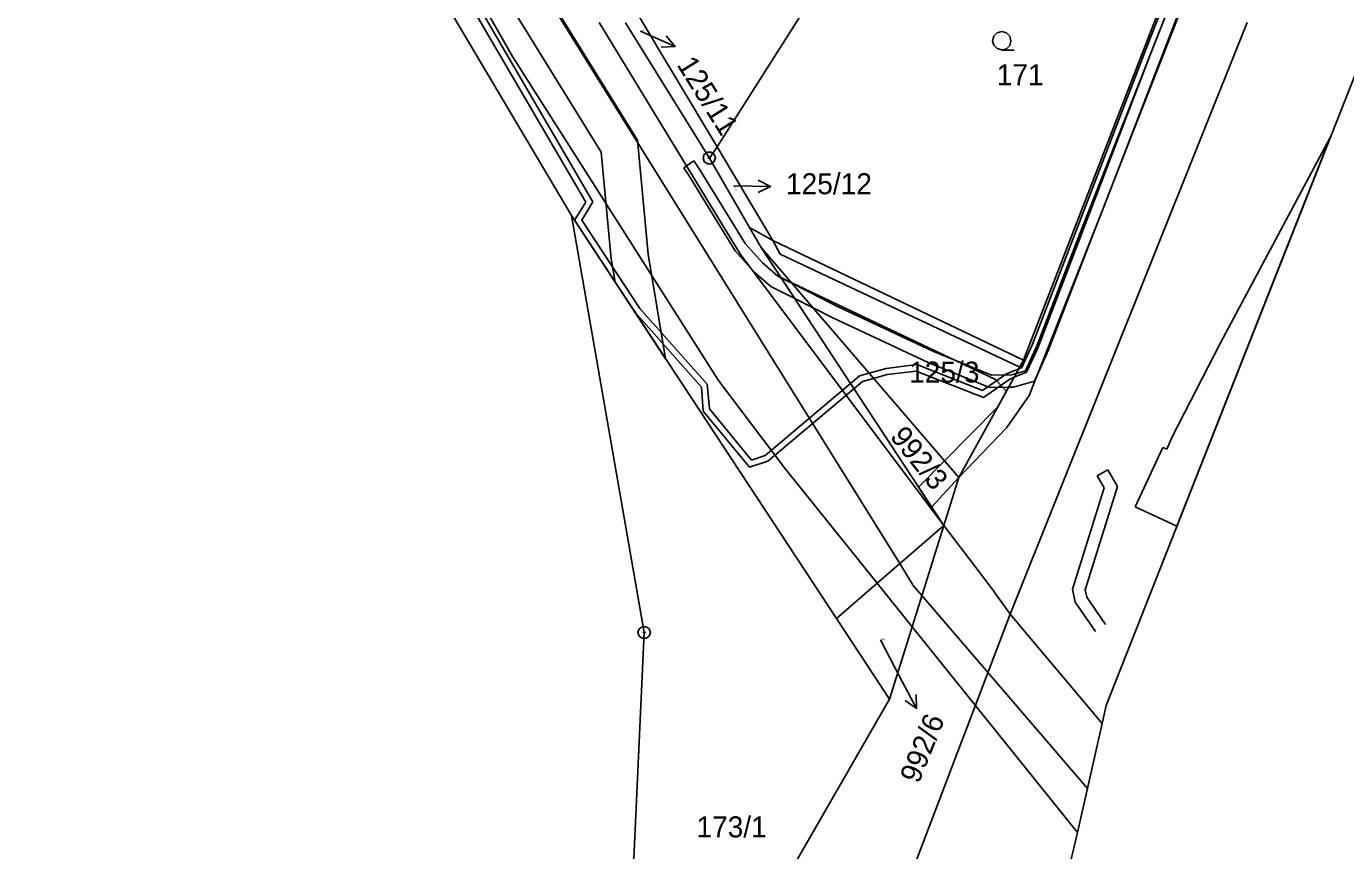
# Model space of a CAD drawing. Extents: x -755359 to -754474, y -1162585 to -1161655.
# Drawn here: x -754834.8 to -754728, y -1161971.6 to -1161904.8 of the extents above; entities that cross this region are included whole.
import ezdxf

# ---------------------------------------------------------------- set-up
doc = ezdxf.new("R2010")
doc.units = 0
for name, color, linetype in [('Vrstva 1', 7, 'Continuous'), ('Vrstva 11', 7, 'Continuous'), ('Vrstva 13', 7, 'Continuous'), ('Vrstva 2', 7, 'Continuous'), ('Vrstva 3', 7, 'Continuous'), ('Vrstva 4', 7, 'Continuous'), ('Vrstva 6', 7, 'Continuous'), ('Vrstva 7', 7, 'Continuous'), ('Vrstva 8', 7, 'Continuous')]:
    doc.layers.add(name, color=color, linetype=linetype)

msp = doc.modelspace()

# ---------------------------------------------------------------- linework, layer by layer
at = {"layer": 'Vrstva 1'}
for p, q in [((-754823.33, -1161865.1), (-754790.69, -1161920.17)), ((-754731.59, -1161873.64), (-754754.1, -1161931.89)), ((-754747.41, -1161959.83), (-754718.58, -1161886.73)), ((-754778.9, -1161914.6), (-754766.52, -1161895.09)), ((-754785.52, -1161903.56), (-754778.9, -1161914.6)), ((-754779.53, -1161915.51), (-754786.32, -1161904.57)), ((-754778.9, -1161914.6), (-754779.53, -1161915.51)), ((-754774.38, -1161922.19), (-754778.9, -1161914.6)), ((-754776.28, -1161921.13), (-754779.53, -1161915.51)), ((-754784.8, -1161953.94), (-754790.69, -1161920.17)), ((-754790.69, -1161920.17), (-754769.25, -1161952.8)), ((-754774.38, -1161922.19), (-754776.28, -1161921.13)), ((-754775.33, -1161922.76), (-754776.28, -1161921.13)), ((-754759.34, -1161941.39), (-754775.33, -1161922.76)), ((-754775.33, -1161922.76), (-754760.56, -1161945.27)), ((-754754.1, -1161931.89), (-754774.38, -1161922.19)), ((-754754.1, -1161931.89), (-754759.34, -1161941.39)), ((-754760.56, -1161945.27), (-754759.34, -1161941.39)), ((-754760.56, -1161945.27), (-754765.94, -1161949.93)), ((-754763.11, -1161953.46), (-754760.56, -1161945.27)), ((-754765.94, -1161949.93), (-754769.25, -1161952.8)), ((-754769.25, -1161952.8), (-754764.95, -1161959.34)), ((-754785.77, -1161974.89), (-754784.8, -1161953.94)), ((-754764.95, -1161959.34), (-754763.11, -1161953.46)), ((-754764.95, -1161959.34), (-754780.44, -1161986.21)), ((-754747.74, -1161961.29), (-754747.41, -1161959.83)), ((-754749.74, -1161970.12), (-754747.74, -1161961.29)), ((-754750.32, -1161972.64), (-754749.74, -1161970.12))]:
    msp.add_line(p, q, dxfattribs=at)
at = {"layer": 'Vrstva 11'}
for p, q in [((-754802.43, -1161886.78), (-754764.12, -1161948.35)), ((-754721.5, -1161894.13), (-754747.41, -1161959.83)), ((-754764.12, -1161948.35), (-754763.02, -1161950.13)), ((-754763.02, -1161950.13), (-754762.32, -1161950.94)), ((-754762.32, -1161950.94), (-754748.93, -1161966.56)), ((-754747.41, -1161959.83), (-754747.74, -1161961.29)), ((-754747.74, -1161961.29), (-754748.93, -1161966.56)), ((-754748.93, -1161966.56), (-754749.74, -1161970.12)), ((-754749.74, -1161970.12), (-754750.32, -1161972.64))]:
    msp.add_line(p, q, dxfattribs=at)
at = {"layer": 'Vrstva 13'}
for p, q in [((-754832.48, -1161837.94), (-754785.36, -1161914.05)), ((-754788.28, -1161915.03), (-754834.82, -1161839.85)), ((-754754.1, -1161931.89), (-754731.59, -1161873.64)), ((-754744.07, -1161906.36), (-754736.26, -1161886.5)), ((-754735.8, -1161886.68), (-754743.61, -1161906.54)), ((-754736.9, -1161891.63), (-754747.54, -1161919.33)), ((-754789.54, -1161919.07), (-754799.99, -1161901.15)), ((-754799.57, -1161900.89), (-754788.96, -1161919.06)), ((-754746.07, -1161912.78), (-754742.45, -1161903.59)), ((-754741.53, -1161903.95), (-754745.13, -1161913.14)), ((-754753.37, -1161930.59), (-754744.07, -1161906.36)), ((-754743.61, -1161906.54), (-754752.98, -1161930.96)), ((-754749.51, -1161921.57), (-754746.07, -1161912.78)), ((-754745.13, -1161913.14), (-754748.57, -1161921.93)), ((-754785.36, -1161914.05), (-754784.49, -1161923.29)), ((-754729.27, -1161913.84), (-754741.69, -1161945.32)), ((-754738.15, -1161930.48), (-754729.27, -1161913.84)), ((-754787.47, -1161923.67), (-754788.28, -1161915.03)), ((-754781.61, -1161916.31), (-754780.79, -1161915.73)), ((-754781.22, -1161916.86), (-754781.61, -1161916.31)), ((-754780.79, -1161915.73), (-754780.38, -1161916.32)), ((-754780.38, -1161916.32), (-754776.64, -1161922.43)), ((-754777.44, -1161923.03), (-754781.22, -1161916.86)), ((-754790.44, -1161920.55), (-754789.54, -1161919.07)), ((-754788.96, -1161919.06), (-754789.85, -1161920.53)), ((-754747.54, -1161919.33), (-754753.65, -1161934.74)), ((-754787.16, -1161925.55), (-754790.44, -1161920.55)), ((-754789.85, -1161920.53), (-754785.15, -1161927.69)), ((-754775.33, -1161922.76), (-754776.28, -1161921.13)), ((-754776.28, -1161921.13), (-754774.38, -1161922.19)), ((-754752.99, -1161930.67), (-754749.51, -1161921.57)), ((-754748.57, -1161921.93), (-754752.07, -1161931.05)), ((-754775.96, -1161924.7), (-754777.44, -1161923.03)), ((-754776.64, -1161922.43), (-754775.26, -1161923.98)), ((-754773.74, -1161925.19), (-754775.33, -1161922.76)), ((-754774.38, -1161922.19), (-754773.79, -1161923.28)), ((-754787.16, -1161925.55), (-754787.47, -1161923.67)), ((-754784.49, -1161923.29), (-754783.07, -1161931.76)), ((-754775.26, -1161923.98), (-754773.99, -1161925.07)), ((-754773.79, -1161923.28), (-754754.41, -1161932.45)), ((-754774.55, -1161925.91), (-754775.96, -1161924.7)), ((-754773.99, -1161925.07), (-754773.72, -1161925.21)), ((-754772.91, -1161925.58), (-754773.74, -1161925.19)), ((-754773.72, -1161925.21), (-754772.85, -1161925.65)), ((-754773.72, -1161925.21), (-754772.62, -1161926.89)), ((-754772.62, -1161926.89), (-754773.72, -1161925.21)), ((-754783.07, -1161931.76), (-754787.16, -1161925.55)), ((-754785.49, -1161928.08), (-754787.16, -1161925.55)), ((-754772.62, -1161926.89), (-754774.55, -1161925.91)), ((-754756.36, -1161933.45), (-754772.91, -1161925.58)), ((-754772.85, -1161925.65), (-754769.16, -1161927.53)), ((-754771.14, -1161927.65), (-754772.62, -1161926.89)), ((-754780.18, -1161934.05), (-754785.49, -1161928.08)), ((-754785.15, -1161927.69), (-754779.7, -1161933.83)), ((-754769.6, -1161928.43), (-754771.14, -1161927.65)), ((-754761.83, -1161932.06), (-754769.6, -1161928.43)), ((-754769.16, -1161927.53), (-754761.43, -1161931.14)), ((-754754.24, -1161932.48), (-754753.37, -1161930.59)), ((-754742.04, -1161938.03), (-754738.15, -1161930.48)), ((-754761.43, -1161931.14), (-754756.68, -1161933.1)), ((-754753.93, -1161932.73), (-754752.99, -1161930.67)), ((-754752.98, -1161930.96), (-754753.86, -1161932.86)), ((-754752.07, -1161931.05), (-754753.21, -1161933.57)), ((-754766.6, -1161932.93), (-754765.23, -1161932.54)), ((-754765.23, -1161932.54), (-754762.74, -1161932.24)), ((-754762.79, -1161932.76), (-754765.13, -1161933.03)), ((-754757.35, -1161934.9), (-754762.79, -1161932.76)), ((-754762.74, -1161932.24), (-754757.42, -1161934.34)), ((-754756.86, -1161934.1), (-754761.83, -1161932.06)), ((-754755.47, -1161932.98), (-754754.48, -1161932.58)), ((-754754.69, -1161932.95), (-754753.93, -1161932.73)), ((-754754.48, -1161932.58), (-754754.24, -1161932.48)), ((-754754.41, -1161932.45), (-754754.1, -1161931.89)), ((-754779.7, -1161933.83), (-754779.53, -1161935.82)), ((-754775.02, -1161939.6), (-754768.11, -1161933.77)), ((-754768.11, -1161933.77), (-754767.38, -1161933.15)), ((-754767.83, -1161934.19), (-754768.11, -1161933.77)), ((-754768.11, -1161933.77), (-754767.83, -1161934.19)), ((-754767.14, -1161933.61), (-754767.83, -1161934.19)), ((-754767.38, -1161933.15), (-754766.6, -1161932.93)), ((-754766.24, -1161933.35), (-754767.14, -1161933.61)), ((-754765.13, -1161933.03), (-754766.24, -1161933.35)), ((-754757.42, -1161934.34), (-754755.47, -1161932.98)), ((-754755.22, -1161933.41), (-754757.35, -1161934.9)), ((-754756.68, -1161933.1), (-754755.07, -1161933.06)), ((-754755.48, -1161934.39), (-754756.36, -1161933.45)), ((-754754.86, -1161933.26), (-754755.22, -1161933.41)), ((-754755.07, -1161933.06), (-754754.69, -1161932.95)), ((-754753.21, -1161933.57), (-754754.91, -1161934.06)), ((-754753.86, -1161932.86), (-754754.86, -1161933.26)), ((-754780.02, -1161936.01), (-754780.18, -1161934.05)), ((-754767.83, -1161934.19), (-754774.8, -1161940.06)), ((-754755.3, -1161934.07), (-754756.86, -1161934.1)), ((-754756.18, -1161935.66), (-754755.48, -1161934.39)), ((-754753.65, -1161934.74), (-754755.44, -1161937.32)), ((-754754.91, -1161934.06), (-754755.3, -1161934.07)), ((-754779.53, -1161935.82), (-754776.13, -1161939.97)), ((-754760.5, -1161940.04), (-754756.18, -1161935.66)), ((-754776.29, -1161940.55), (-754780.02, -1161936.01)), ((-754755.44, -1161937.32), (-754759.34, -1161941.39)), ((-754742.51, -1161939.07), (-754742.04, -1161938.03)), ((-754745.07, -1161943.74), (-754742.83, -1161938.94)), ((-754742.83, -1161938.94), (-754742.51, -1161939.07)), ((-754774.8, -1161940.06), (-754776.29, -1161940.55)), ((-754776.13, -1161939.97), (-754775.02, -1161939.6)), ((-754762.59, -1161942.17), (-754760.5, -1161940.04)), ((-754748.14, -1161941.25), (-754747.28, -1161940.75)), ((-754747.57, -1161942.22), (-754748.14, -1161941.25)), ((-754747.28, -1161940.75), (-754746.49, -1161942.1)), ((-754761.54, -1161943.78), (-754762.59, -1161942.17)), ((-754759.34, -1161941.39), (-754761.54, -1161943.78)), ((-754750.14, -1161950.41), (-754747.57, -1161942.22)), ((-754746.49, -1161942.1), (-754749.1, -1161950.47)), ((-754741.69, -1161945.32), (-754745.07, -1161943.74)), ((-754749.92, -1161951.47), (-754750.14, -1161950.41)), ((-754749.1, -1161950.47), (-754748.98, -1161951.07)), ((-754748.27, -1161953.85), (-754749.92, -1161951.47)), ((-754748.98, -1161951.07), (-754747.47, -1161953.27))]:
    msp.add_line(p, q, dxfattribs=at)
at = {"layer": 'Vrstva 3'}
msp.add_lwpolyline([(-754755.85, -1161906.75), (-754756.23, -1161906.65), (-754756.5, -1161906.38), (-754756.6, -1161906.01), (-754756.5, -1161905.64), (-754756.23, -1161905.37), (-754755.86, -1161905.27), (-754755.49, -1161905.37), (-754755.22, -1161905.64), (-754755.12, -1161906.02), (-754755.22, -1161906.4), (-754755.49, -1161906.67), (-754755.87, -1161906.77), (-754754.87, -1161906.77)], dxfattribs=at)
at = {"layer": 'Vrstva 4'}
for p, q in [((-754807.06, -1161886.86), (-754795.46, -1161907.28)), ((-754777, -1161923.33), (-754788.45, -1161904.52)), ((-754795.46, -1161907.28), (-754778.8, -1161933.52)), ((-754760.56, -1161945.27), (-754777, -1161923.33)), ((-754778.8, -1161933.52), (-754773.44, -1161940.6)), ((-754773.44, -1161940.6), (-754765.94, -1161949.93)), ((-754756.74, -1161950.25), (-754760.56, -1161945.27)), ((-754765.94, -1161949.93), (-754763.11, -1161953.46)), ((-754755.18, -1161952.44), (-754756.74, -1161950.25)), ((-754747.74, -1161961.29), (-754755.18, -1161952.44)), ((-754749.74, -1161970.12), (-754763.11, -1161953.46))]:
    msp.add_line(p, q, dxfattribs=at)
at = {"layer": 'Vrstva 6'}
for p in [(-754736, -1161904.52), (-754762.88, -1161972.64)]:
    msp.add_line(p, (-754755.18, -1161952.44), dxfattribs=at)
at = {"layer": 'Vrstva 7'}
for p, q in [((-754785.13, -1161905.23), (-754785.05, -1161905.27)), ((-754782.309, -1161906.489), (-754785.05, -1161905.27)), ((-754774.58, -1161917.822), (-754777.58, -1161917.77)), ((-754765.69, -1161954.53), (-754764.17, -1161957.43)), ((-754762.762, -1161960.079), (-754764.17, -1161957.43))]:
    msp.add_line(p, q, dxfattribs=at)
for points in [[(-754783.019, -1161905.626), (-754782.309, -1161906.489), (-754783.426, -1161906.539)], [(-754775.572, -1161917.305), (-754774.58, -1161917.822), (-754775.589, -1161918.305)], [(-754762.79, -1161958.962), (-754762.762, -1161960.079), (-754763.673, -1161959.431)]]:
    msp.add_lwpolyline(points, dxfattribs=at)
at = {"layer": 'Vrstva 8'}
for p, q in [((-754779.65, -1161915.51), (-754779.41, -1161915.51)), ((-754784.92, -1161953.94), (-754784.68, -1161953.94))]:
    msp.add_line(p, q, dxfattribs=at)
for points in [[(-754779.38, -1161915.03), (-754779.13, -1161915.21), (-754779.03, -1161915.5), (-754779.13, -1161915.79), (-754779.38, -1161915.97), (-754779.69, -1161915.97), (-754779.94, -1161915.79), (-754780.04, -1161915.5), (-754779.94, -1161915.21), (-754779.69, -1161915.03)], [(-754784.65, -1161953.46), (-754784.4, -1161953.64), (-754784.3, -1161953.93), (-754784.4, -1161954.22), (-754784.65, -1161954.4), (-754784.96, -1161954.4), (-754785.21, -1161954.22), (-754785.31, -1161953.93), (-754785.21, -1161953.64), (-754784.96, -1161953.46)]]:
    msp.add_lwpolyline(points, close=True, dxfattribs=at)

# ---------------------------------------------------------------- texts
at = {"layer": 'Vrstva 2'}
for s, height, p in [('125/11', 0.1, (-754785.107, -1161905.23)), ('171', 1.7, (-754756.267, -1161909.61)), ('125/3', 1.7, (-754763.357, -1161933.69)), ('992/6', 0.1, (-754765.676, -1161954.53)), ('173/1', 1.7, (-754780.577, -1161970.52))]:
    msp.add_text(s, height=height, dxfattribs=at).set_placement(p)
for s, height, rotation, p in [('125/12', 0.1, 297.02132, (-754777.57, -1161917.791)), ('992/3', 1.7, 308.70966, (-754764.972, -1161938.095))]:
    msp.add_text(s, height=height, rotation=rotation, dxfattribs=at).set_placement(p)
at = {"layer": 'Vrstva 7'}
for s, rotation, p in [('125/11', 302.00605, (-754782.213, -1161907.944)), ('992/6', 68.01009, (-754762.589, -1161966.241))]:
    msp.add_text(s, height=1.7, rotation=rotation, dxfattribs=at).set_placement(p)
msp.add_text('125/12', height=1.7, dxfattribs=at).set_placement((-754773.327, -1161918.44))

doc.saveas('drawing.dxf')
